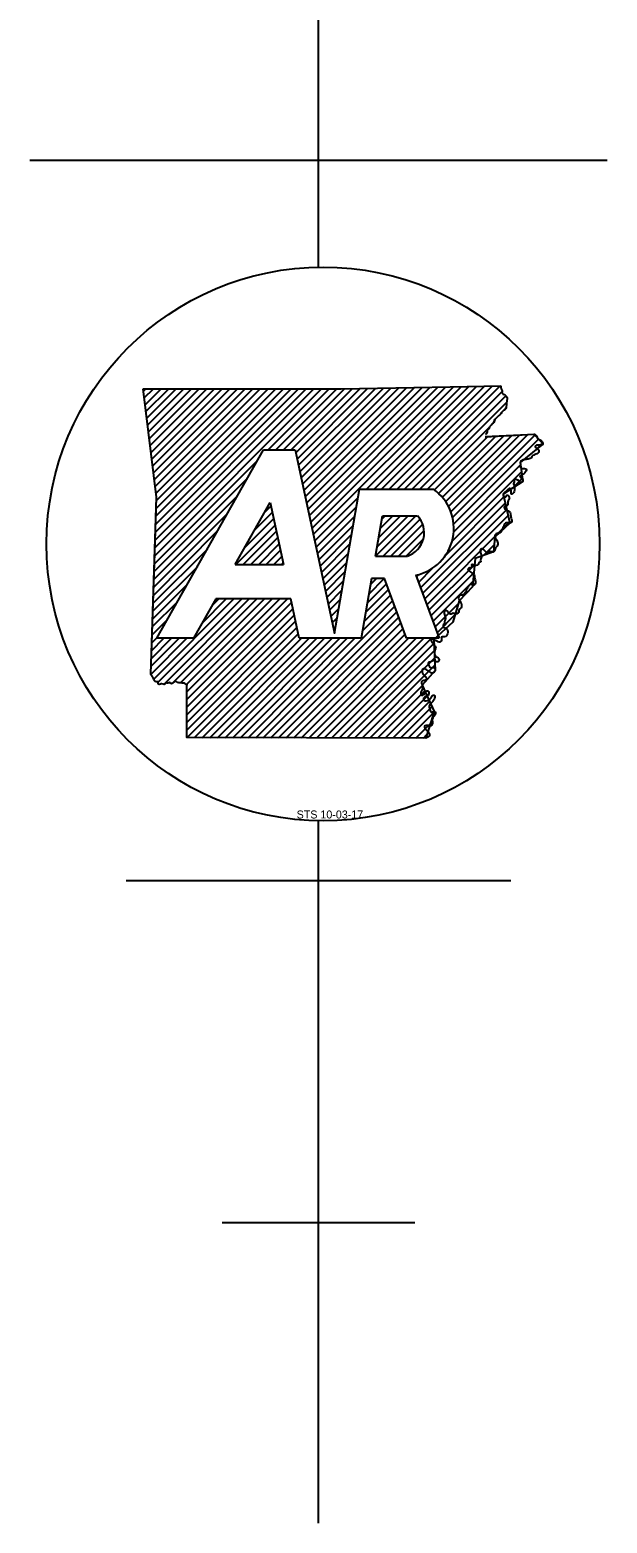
# Model space of a CAD drawing. Extents: x -43543 to 34500, y -13675 to 11152.
# Drawn here: x 16425 to 16951, y -3693 to -2333 of the extents above; entities that cross this region are included whole.
import ezdxf

# ---------------------------------------------------------------- set-up
doc = ezdxf.new("R2010")
doc.units = 0
doc.layers.add('R_Annotation', color=7, linetype='Continuous')

msp = doc.modelspace()

# ---------------------------------------------------------------- linework, layer by layer
at = {"layer": 'R_Annotation'}
for p, q in [((16687.9, -2548.9), (16687.9, -973)), ((16424.7, -2451.4), (16951, -2451.4)), ((16528.2, -2661.8), (16530.4, -2659.6)), ((16529, -2667.9), (16537.4, -2659.6)), ((16529.8, -2674.1), (16544.3, -2659.6)), ((16530.5, -2680.3), (16551.3, -2659.6)), ((16531.3, -2686.5), (16558.2, -2659.6)), ((16532.1, -2692.7), (16565.2, -2659.6)), ((16532.9, -2698.9), (16572.2, -2659.6)), ((16533.6, -2705.1), (16579.1, -2659.6)), ((16534.4, -2711.3), (16586.1, -2659.6)), ((16535.2, -2717.5), (16593, -2659.6)), ((16535.9, -2723.7), (16600, -2659.6)), ((16536.7, -2729.9), (16607, -2659.6)), ((16537.5, -2736.1), (16613.9, -2659.6)), ((16538.3, -2742.3), (16620.9, -2659.6)), ((16538.5, -2811.7), (16690.7, -2659.5)), ((16538.7, -2804.5), (16683.7, -2659.5)), ((16539, -2797.3), (16676.7, -2659.5)), ((16539, -2748.5), (16627.9, -2659.6)), ((16539.2, -2790.1), (16669.7, -2659.5)), ((16539.4, -2782.9), (16662.8, -2659.6)), ((16539.7, -2775.7), (16655.8, -2659.6)), ((16539.8, -2754.7), (16634.8, -2659.6)), ((16539.9, -2768.5), (16648.8, -2659.6)), ((16540.2, -2761.3), (16641.8, -2659.6)), ((16641.9, -2715.2), (16697.7, -2659.5)), ((16648.9, -2715.2), (16704.7, -2659.5)), ((16655.9, -2715.2), (16711.7, -2659.4)), ((16662.8, -2715.2), (16718.8, -2659.3)), ((16667.2, -2717.9), (16725.8, -2659.2)), ((16668.4, -2723.6), (16732.9, -2659.1)), ((16669.6, -2729.3), (16740, -2659)), ((16670.8, -2735.1), (16747.1, -2658.9)), ((16672.1, -2740.8), (16754.1, -2658.7)), ((16673.3, -2746.5), (16761.2, -2658.6)), ((16674.5, -2752.3), (16768.3, -2658.5)), ((16675.8, -2758), (16775.4, -2658.4)), ((16677, -2763.8), (16782.4, -2658.3)), ((16678.2, -2769.5), (16789.5, -2658.2)), ((16679.4, -2775.2), (16796.6, -2658.1)), ((16680.7, -2781), (16803.7, -2658)), ((16681.9, -2786.7), (16810.8, -2657.8)), ((16683.1, -2792.4), (16817.9, -2657.7)), ((16731.5, -2751), (16825, -2657.5)), ((16738.5, -2751), (16832.2, -2657.3)), ((16745.4, -2751), (16839.3, -2657.2)), ((16752.4, -2751), (16846.4, -2657)), ((16759.4, -2751), (16853.5, -2656.9)), ((16766.3, -2751), (16855.1, -2662.3)), ((16773.3, -2751), (16858.5, -2665.9)), ((16780.3, -2751), (16859.4, -2671.9)), ((16787.2, -2751), (16843.5, -2694.8)), ((16793.6, -2751.7), (16842.1, -2703.1)), ((16797.4, -2754.8), (16849.4, -2702.8)), ((16800.8, -2758.4), (16856.8, -2702.4)), ((16803.8, -2762.3), (16864.1, -2702)), ((16806.4, -2766.7), (16871.5, -2701.6)), ((16808.5, -2771.6), (16878.8, -2701.3)), ((16810.1, -2776.9), (16885.4, -2701.6)), ((16811, -2782.9), (16888.7, -2705.3)), ((16540.6, -2886.8), (16637.7, -2715.2)), ((16637.7, -2715.2), (16666.6, -2715.2)), ((16885.6, -2715.4), (16891.9, -2709)), ((16538.2, -2818.9), (16632.2, -2724.9)), ((16811.1, -2789.9), (16872, -2728.9)), ((16538, -2826.1), (16623.1, -2741)), ((16809.6, -2798.3), (16872.8, -2735.1)), ((16865, -2749.8), (16873.6, -2741.2)), ((16537.8, -2833.3), (16614.1, -2757)), ((16684.4, -2798.2), (16723.9, -2758.7)), ((16725.2, -2751), (16792.7, -2751)), ((16803.6, -2811.3), (16856.8, -2758.1)), ((16537.5, -2840.5), (16605, -2773.1)), ((16612, -2819.5), (16643.8, -2763.3)), ((16629.8, -2788.1), (16645.7, -2772.2)), ((16638.9, -2772.1), (16644.5, -2766.5)), ((16685.6, -2803.9), (16722.4, -2767.1)), ((16780.9, -2841), (16858.1, -2763.8)), ((16782.7, -2846.1), (16859.4, -2769.4)), ((16612.4, -2819.5), (16648.2, -2783.7)), ((16620.7, -2804.2), (16646.9, -2777.9)), ((16686.8, -2809.7), (16720.9, -2775.5)), ((16688, -2815.4), (16719.5, -2784)), ((16739.9, -2811.9), (16776.5, -2775.2)), ((16741.3, -2803.5), (16769.6, -2775.2)), ((16742.8, -2795.1), (16762.6, -2775.2)), ((16744.3, -2786.6), (16755.6, -2775.2)), ((16745.7, -2778.2), (16748.7, -2775.2)), ((16746.2, -2775.2), (16777.9, -2775.2)), ((16746.9, -2811.9), (16780.4, -2778.3)), ((16753.8, -2811.9), (16782.8, -2782.9)), ((16784.6, -2851.2), (16860.7, -2775.1)), ((16786.5, -2856.2), (16862, -2780.7)), ((16537.3, -2847.7), (16595.9, -2789.1)), ((16619.3, -2819.5), (16649.4, -2789.4)), ((16626.3, -2819.5), (16650.6, -2795.2)), ((16633.3, -2819.5), (16651.9, -2800.9)), ((16689.3, -2821.1), (16718, -2792.4)), ((16690.5, -2826.9), (16716.5, -2800.8)), ((16760.8, -2811.9), (16784.1, -2788.6)), ((16767.8, -2811.9), (16783.5, -2796.2)), ((16537, -2854.9), (16586.8, -2805.2)), ((16640.2, -2819.5), (16653.1, -2806.6)), ((16647.2, -2819.5), (16654.3, -2812.4)), ((16691.7, -2832.6), (16715.1, -2809.3)), ((16739.9, -2811.9), (16768.8, -2811.9)), ((16838.2, -2811.5), (16848, -2801.8)), ((16536.8, -2862.1), (16577.7, -2821.3)), ((16612, -2819.5), (16655.8, -2819.5)), ((16654.2, -2819.5), (16655.5, -2818.1)), ((16692.9, -2838.3), (16713.6, -2817.7)), ((16694.2, -2844.1), (16712.1, -2826.1)), ((16779, -2835.9), (16792.2, -2822.6)), ((16788.4, -2861.3), (16830.2, -2819.5)), ((16790.3, -2866.4), (16829.4, -2827.3)), ((16536.6, -2869.3), (16568.6, -2837.3)), ((16695.4, -2849.8), (16710.6, -2834.6)), ((16732.4, -2854.6), (16749.8, -2837.2)), ((16733.9, -2846.2), (16747.8, -2832.3)), ((16735.3, -2837.7), (16740.8, -2832.3)), ((16748, -2832.3), (16736.3, -2832.3)), ((16768.2, -2886.8), (16748, -2832.3)), ((16776.6, -2829.3), (16797.8, -2886.8)), ((16777.1, -2830.8), (16779.2, -2828.7)), ((16792.1, -2871.5), (16828.6, -2835)), ((16536.3, -2876.5), (16559.5, -2853.4)), ((16537.6, -2924), (16610.8, -2850.8)), ((16541.7, -2926.9), (16617.8, -2850.8)), ((16546.7, -2928.8), (16624.7, -2850.8)), ((16555, -2927.5), (16631.7, -2850.8)), ((16562.1, -2927.4), (16638.7, -2850.8)), ((16567.6, -2928.9), (16645.6, -2850.8)), ((16567.8, -2942.6), (16659.6, -2850.8)), ((16567.8, -2935.6), (16652.6, -2850.8)), ((16567.8, -2949.5), (16663.2, -2854.1)), ((16594.3, -2850.8), (16573.9, -2886.8)), ((16581.8, -2872.9), (16603.8, -2850.8)), ((16590.9, -2856.8), (16596.9, -2850.8)), ((16662.5, -2850.8), (16594.3, -2850.8)), ((16696.6, -2855.6), (16709.2, -2843)), ((16697.9, -2861.3), (16707.7, -2851.4)), ((16728, -2879.9), (16755.5, -2852.5)), ((16729.5, -2871.5), (16753.6, -2847.4)), ((16730.9, -2863), (16751.7, -2842.3)), ((16794, -2876.6), (16815.4, -2855.2)), ((16567.8, -2956.5), (16664.5, -2859.9)), ((16567.9, -2963.4), (16665.7, -2865.6)), ((16637.5, -2977.3), (16757.3, -2857.5)), ((16644.5, -2977.4), (16759.2, -2862.6)), ((16651.4, -2977.4), (16761.1, -2867.7)), ((16699.1, -2867), (16706.2, -2859.9)), ((16700.3, -2872.8), (16704.8, -2868.3)), ((16795.9, -2881.7), (16812.4, -2865.2)), ((16536.1, -2883.7), (16550.4, -2869.4)), ((16567.9, -2970.4), (16666.9, -2871.3)), ((16568, -2977.2), (16668.2, -2877.1)), ((16658.4, -2977.4), (16763, -2872.8)), ((16665.4, -2977.4), (16764.9, -2877.9)), ((16701.5, -2878.5), (16703.3, -2876.8)), ((16535, -2919.7), (16567.8, -2886.8)), ((16535.1, -2912.6), (16560.9, -2886.8)), ((16535.4, -2905.4), (16553.9, -2886.8)), ((16535.6, -2898.2), (16546.9, -2886.8)), ((16535.9, -2891), (16541.3, -2885.5)), ((16573.9, -2886.8), (16540.6, -2886.8)), ((16574.9, -2977.2), (16669.4, -2882.8)), ((16581.9, -2977.3), (16672.3, -2886.8)), ((16588.9, -2977.3), (16679.3, -2886.8)), ((16595.8, -2977.3), (16686.3, -2886.8)), ((16602.8, -2977.3), (16693.2, -2886.8)), ((16609.7, -2977.3), (16700.2, -2886.8)), ((16616.7, -2977.3), (16707.2, -2886.8)), ((16623.6, -2977.3), (16714.1, -2886.8)), ((16630.6, -2977.3), (16721.1, -2886.8)), ((16726.8, -2886.8), (16670.2, -2886.8)), ((16672.3, -2977.4), (16766.7, -2883)), ((16679.3, -2977.4), (16769.8, -2886.8)), ((16686.2, -2977.4), (16776.8, -2886.8)), ((16693.2, -2977.4), (16783.8, -2886.8)), ((16700.1, -2977.4), (16790.7, -2886.8)), ((16707.1, -2977.5), (16793.1, -2891.5)), ((16797.8, -2886.8), (16768.2, -2886.8)), ((16714, -2977.5), (16793.4, -2898.1)), ((16721, -2977.5), (16793.7, -2904.8)), ((16727.9, -2977.5), (16794, -2911.4)), ((16734.9, -2977.5), (16782.6, -2929.8)), ((16741.8, -2977.5), (16784.7, -2934.6)), ((16748.8, -2977.5), (16786.9, -2939.5)), ((16755.8, -2977.5), (16789, -2944.3)), ((16762.7, -2977.6), (16791.2, -2949.1)), ((16769.7, -2977.6), (16793, -2954.3)), ((16776.6, -2977.6), (16789.8, -2964.4)), ((16783.6, -2977.6), (16786.7, -2974.5)), ((16687.9, -3692.5), (16687.9, -3053)), ((16512.4, -3107.3), (16863.3, -3107.3)), ((16600.1, -3418.9), (16775.6, -3418.9))]:
    msp.add_line(p, q, dxfattribs=at)
for points in [[(16527.9, -2659.6), (16624, -2659.6), (16708.4, -2659.5), (16807.9, -2657.9), (16854, -2656.8)], [(16538.6, -2809), (16540.2, -2758.3), (16527.9, -2659.6)], [(16528, -2659.6), (16624.1, -2659.6), (16708.4, -2659.5), (16807.9, -2657.9), (16854, -2656.8)], [(16534.9, -2919.6), (16540.3, -2758.3), (16528, -2659.6)], [(16884.2, -2701), (16892.5, -2709.7), (16871.8, -2726.7), (16874, -2743.9), (16856.2, -2755.7), (16862.3, -2782.1), (16848.6, -2794.6), (16847.4, -2808.2), (16830.7, -2814.2), (16828.1, -2839.9), (16816.1, -2852.7), (16810.4, -2872), (16792.9, -2888), (16794.2, -2916.1), (16782.4, -2929.4), (16793.2, -2953.6), (16785.7, -2977.6)], [(16839.7, -2703.3), (16884.8, -2700.9)], [(16839.7, -2703.2), (16884.8, -2701)], [(16666.6, -2715.2), (16702.3, -2882.2), (16725.2, -2751)], [(16643.8, -2763.3), (16655.8, -2819.5)], [(16739.9, -2811.9), (16746.2, -2775.2)], [(16534.9, -2919.6), (16538.6, -2809)], [(16736.3, -2832.3), (16726.8, -2886.8)], [(16670.2, -2886.8), (16662.5, -2850.8)], [(16785.7, -2977.6), (16567.9, -2977.2), (16567.8, -2929.1)], [(16785.7, -2977.6), (16567.9, -2977.2), (16567.8, -2929.2)]]:
    msp.add_lwpolyline(points, dxfattribs=at)
msp.add_ellipse((16692, -2800.9), major_axis=(252.1, 0), ratio=0.999976, dxfattribs=at)
for centre, major_axis, start_param, end_param in [((16767.6, -2786.7), (-43.6, 0), 1.777838, 4.099264), ((16761.9, -2790.7), (-22.3, 0), 1.887169, 3.90762)]:
    msp.add_ellipse(centre, major_axis=major_axis, ratio=0.999987, start_param=start_param, end_param=end_param, dxfattribs=at)
for points in [[(16854, -2656.8), (16854.3, -2659.5), (16855.1, -2660.8), (16855.2, -2663.3), (16856.2, -2664.4), (16858, -2665.5), (16859.5, -2667.2), (16859.9, -2669.2), (16859.4, -2671.3), (16859.3, -2673.6), (16859, -2675.7), (16858.6, -2677.4), (16857.3, -2679), (16855.9, -2680), (16854.7, -2681.2), (16853.8, -2682.6), (16852.2, -2684), (16850.7, -2685.5), (16849.4, -2686.8), (16848.1, -2688.5), (16847.5, -2690.3), (16846.2, -2691.6), (16845.1, -2692.8), (16843.7, -2694.4), (16843, -2696), (16841.7, -2697.8), (16841.3, -2699.6), (16840.5, -2701), (16840.4, -2701.3)], [(16854, -2656.8), (16854.3, -2659.5), (16855.1, -2660.8), (16855.2, -2663.3), (16856.2, -2664.4), (16858, -2665.5), (16859.5, -2667.2), (16859.9, -2669.2), (16859.4, -2671.3), (16859.3, -2673.6), (16859, -2675.6), (16858.7, -2677.5), (16857.3, -2679), (16855.9, -2680), (16854.6, -2681.3), (16853.8, -2682.6), (16852.2, -2684), (16850.7, -2685.5), (16849.4, -2686.8), (16848.2, -2688.5), (16847.6, -2690.3), (16846.2, -2691.6), (16845.1, -2692.8), (16843.7, -2694.4), (16843, -2696), (16841.6, -2697.8), (16841.3, -2699.6), (16840.4, -2701.1), (16840.4, -2701.3)], [(16884.2, -2701), (16884.8, -2701), (16886.8, -2703.1), (16887.7, -2704.9), (16889.1, -2705.9), (16890.6, -2706.4), (16891.7, -2707.8), (16892.4, -2709.3), (16892, -2710.6), (16890.3, -2710.7), (16888.5, -2711), (16886.7, -2710.9), (16885.3, -2712.2), (16886.6, -2713.7), (16888.3, -2715.2), (16888.8, -2716.8), (16887.9, -2718.3), (16885.9, -2719.2), (16884.1, -2719.9), (16882.4, -2721.3), (16881.6, -2722.7), (16879.8, -2723.3), (16877.9, -2723.8), (16876.3, -2724), (16874.4, -2724.4), (16872.5, -2725.3), (16871.8, -2726.8), (16872, -2729), (16871.9, -2731.3), (16873.9, -2732.1), (16875.6, -2732.2), (16877.3, -2733), (16877.1, -2734.3), (16875.9, -2736), (16874.4, -2737.3), (16872.9, -2738), (16871.5, -2739.2), (16872, -2740.5), (16873.2, -2741.3), (16874.1, -2742.7), (16874, -2743.9), (16872.6, -2744.8), (16871, -2744.4), (16869.9, -2742.9), (16868.6, -2742.5), (16867.5, -2741.9), (16866.2, -2742.7), (16866.2, -2744.4), (16865.7, -2746.3), (16866.1, -2747.6), (16866.6, -2749.5), (16866.6, -2751), (16866.1, -2753), (16865.1, -2755.1), (16863.9, -2755.7), (16863.4, -2753.5), (16863.2, -2751.6), (16862.5, -2750.5), (16861.5, -2750.5), (16860.3, -2751.4), (16858.9, -2752.8), (16857.2, -2754.3), (16856.2, -2755.7), (16856.7, -2757.6), (16858, -2758), (16859, -2757.7), (16859.6, -2756.5), (16860.5, -2756.4), (16861.5, -2758.2)], [(16861.5, -2758.2), (16861.8, -2759.9), (16860.8, -2761.7), (16860.4, -2763.6), (16860.5, -2765.4), (16858.6, -2766.4), (16857, -2767.6), (16858, -2769.1), (16859.8, -2770.4), (16861.5, -2771.3), (16862.6, -2772.4), (16862.9, -2774.8), (16863.3, -2776.4), (16863.9, -2778.5), (16864.1, -2780), (16863, -2781.8), (16861.8, -2782.1), (16860.4, -2781.7), (16858.9, -2781.6), (16857.7, -2782.7), (16856.8, -2784.4), (16855.9, -2786.1), (16855.2, -2787.5), (16854.6, -2789.1), (16853.3, -2790.9), (16851.7, -2791.1), (16849.8, -2791.6), (16848.6, -2792.9), (16848.8, -2795.1), (16849.9, -2796.6), (16850.7, -2798.4), (16851.3, -2800.1), (16851, -2802.1), (16850.2, -2803.6), (16849.1, -2804.5), (16848.6, -2806.4), (16847.8, -2807.8), (16847.2, -2808.3), (16845.7, -2808.2), (16844.2, -2807.9), (16842.9, -2808), (16841.7, -2808.6), (16840.4, -2808.2), (16839.1, -2806.8), (16838, -2805.7), (16836.8, -2805.3), (16835.5, -2806), (16835.4, -2807.9), (16835.9, -2809.9), (16836.5, -2812.7), (16835.9, -2814.3), (16835.7, -2817.1)], [(16835.7, -2817.1), (16833.7, -2818.7), (16832.7, -2820.3), (16827.4, -2819.8), (16827.6, -2821.7), (16825.7, -2822.7), (16824, -2823.9), (16825, -2825.3), (16826.8, -2826.6), (16828.6, -2827.6), (16829.7, -2828.6), (16830, -2831.1), (16830.3, -2832.6), (16830.9, -2834.8), (16831.1, -2836.2), (16830, -2838), (16828.8, -2838.4), (16827.5, -2837.9), (16826, -2837.8), (16824.7, -2839), (16823.8, -2840.7), (16822.9, -2842.4), (16822.3, -2843.8), (16821.6, -2845.3), (16820.3, -2847.1), (16818.7, -2847.4), (16816.8, -2847.9), (16815.7, -2849.2), (16815.9, -2851.4), (16816.9, -2852.9), (16817.7, -2854.7), (16818.3, -2856.3), (16818.1, -2858.3), (16817.2, -2859.8), (16816.2, -2860.7), (16815.7, -2862.6), (16814.9, -2864.1), (16814.2, -2864.5), (16812.8, -2864.4), (16811.2, -2864.1), (16809.9, -2864.2), (16808.7, -2864.9), (16807.4, -2864.4), (16806.1, -2863), (16805, -2862), (16803.8, -2861.5), (16802.6, -2862.2), (16802.4, -2864.2), (16803, -2866.2), (16803.5, -2868.9), (16803, -2870.6), (16802.8, -2873.3)], [(16802.8, -2873.3), (16802.6, -2873.4), (16801.6, -2874.8), (16802.2, -2876.9), (16804.5, -2877.7), (16805.5, -2879.7), (16805.6, -2881.5), (16804.9, -2883.9), (16803.8, -2885.1), (16801.7, -2885.5), (16800.1, -2885.8), (16799.9, -2888.6), (16799.1, -2889.9), (16797.9, -2890.3), (16796.1, -2889.5), (16795, -2889), (16793.7, -2888.4), (16792.1, -2887.5), (16790.8, -2887.6), (16791.2, -2890.2), (16791.3, -2890.3), (16792.7, -2892.3), (16794.1, -2893.9), (16794.8, -2895.7)], [(16802.8, -2873.3), (16802.6, -2873.4), (16801.6, -2874.8), (16802.2, -2876.9), (16804.5, -2877.7), (16805.5, -2879.7), (16805.6, -2881.5), (16804.9, -2883.9), (16803.8, -2885.1), (16801.7, -2885.5), (16800.1, -2885.8), (16799.9, -2888.6), (16799.1, -2889.9), (16797.9, -2890.3), (16796.1, -2889.5), (16795, -2889), (16793.7, -2888.4), (16792.1, -2887.5), (16790.8, -2887.6), (16791.2, -2890.2), (16791.3, -2890.3), (16792.7, -2892.3), (16794.1, -2893.9), (16794.8, -2895.7)], [(16794.8, -2895.7), (16794.2, -2897.1), (16793.5, -2899.4), (16793.7, -2901.4), (16794.6, -2903.2), (16796, -2904.1), (16797.6, -2905.5), (16797.5, -2907.6), (16796.6, -2908.3), (16794.5, -2907.8), (16792.9, -2907.1), (16791.5, -2907.5), (16789.7, -2908.4), (16788.3, -2908.6), (16788.4, -2911.5), (16790.2, -2913.5), (16791.8, -2913.5), (16793.7, -2913.7), (16794.3, -2915.8), (16793.2, -2917.6), (16791.5, -2918.5), (16789.2, -2917.4), (16787.6, -2916.3), (16786, -2915.2), (16784, -2914.7), (16782.8, -2914.9), (16782.3, -2917.4), (16783.3, -2919.7), (16784.8, -2921.3), (16786.2, -2923.3), (16786, -2924.8), (16784.9, -2925.2), (16783, -2925.6), (16781.9, -2926.2), (16781.6, -2926.6), (16782.2, -2928.7), (16782.7, -2930.9), (16782.7, -2932.6), (16782.1, -2934), (16781.1, -2936.4), (16781.2, -2938), (16781.9, -2938.7), (16782.8, -2938.5), (16784, -2937.7), (16784.8, -2936.7), (16785.4, -2935.5), (16786.6, -2934.5), (16788.2, -2935.4), (16788.5, -2937.2), (16787.7, -2938.8), (16786.4, -2939.6), (16784.9, -2940.2), (16783.7, -2941.4), (16784, -2943), (16784.9, -2943.8), (16787.2, -2943.4), (16788.6, -2942.7), (16789.5, -2942), (16790.5, -2940.9), (16791, -2939.9), (16791.8, -2938.8), (16793.2, -2938.5), (16793.8, -2939.4), (16793.5, -2941.4), (16792.7, -2943.4), (16791.6, -2945), (16790.3, -2946.1), (16788.8, -2948.5), (16789.1, -2950.8), (16789.7, -2952.7), (16790.5, -2954), (16791.9, -2953.8), (16793.5, -2953.6), (16794.5, -2954.3), (16794.4, -2956), (16793.2, -2957.7), (16792.1, -2959.2), (16791.5, -2961.3), (16791.7, -2962.8), (16791.7, -2964.1), (16791.2, -2965.7), (16790.4, -2966.5), (16788.2, -2966.5), (16785.9, -2966.2), (16784.6, -2966.9), (16784.9, -2968.9), (16786.2, -2970.4), (16787.2, -2971.2), (16788.5, -2972.8), (16789.1, -2974.2), (16789, -2975.4), (16788.1, -2976.4), (16785.7, -2977.6)], [(16794.8, -2895.7), (16794.2, -2897.1), (16793.5, -2899.4), (16793.7, -2901.4), (16794.6, -2903.2), (16796, -2904.1), (16797.6, -2905.5), (16797.5, -2907.6), (16796.6, -2908.3), (16794.5, -2907.8), (16792.9, -2907.1), (16791.5, -2907.5), (16789.7, -2908.4), (16788.3, -2908.6), (16788.4, -2911.5), (16790.2, -2913.5), (16791.8, -2913.5), (16793.7, -2913.7), (16794.3, -2915.8), (16793.2, -2917.6), (16791.5, -2918.5), (16789.2, -2917.4), (16787.6, -2916.3), (16786, -2915.2), (16784, -2914.7), (16782.8, -2914.9), (16782.3, -2917.4), (16783.3, -2919.7), (16784.8, -2921.3), (16786.2, -2923.3), (16786, -2924.8), (16784.9, -2925.2), (16783, -2925.6), (16781.9, -2926.2), (16781.6, -2926.6), (16782.2, -2928.7), (16782.7, -2930.9), (16782.7, -2932.6), (16782.1, -2934), (16781.1, -2936.4), (16781.2, -2938), (16781.9, -2938.7), (16782.8, -2938.5), (16784, -2937.7), (16784.8, -2936.7), (16785.4, -2935.5), (16786.6, -2934.5), (16788.2, -2935.4), (16788.5, -2937.2), (16787.7, -2938.8), (16786.4, -2939.6), (16784.9, -2940.2), (16783.7, -2941.4), (16784, -2943), (16784.9, -2943.8), (16787.2, -2943.4), (16788.6, -2942.7), (16789.5, -2942), (16790.5, -2940.9), (16791, -2939.9), (16791.8, -2938.8), (16793.2, -2938.5), (16793.8, -2939.4), (16793.5, -2941.4), (16792.7, -2943.4), (16791.6, -2945), (16790.3, -2946.1), (16788.8, -2948.5), (16789.1, -2950.8), (16789.7, -2952.7), (16790.5, -2954), (16791.9, -2953.8), (16793.5, -2953.6), (16794.5, -2954.3), (16794.4, -2956), (16793.2, -2957.7), (16792.1, -2959.2), (16791.5, -2961.3), (16791.7, -2962.8), (16791.7, -2964.1), (16791.2, -2965.7), (16790.4, -2966.5), (16788.2, -2966.5), (16785.9, -2966.2), (16784.6, -2966.9), (16784.9, -2968.9), (16786.2, -2970.4), (16787.2, -2971.2), (16788.5, -2972.8), (16789.1, -2974.2), (16789, -2975.4), (16788.1, -2976.4), (16785.7, -2977.6)], [(16567.8, -2929.1), (16568, -2929.3), (16566.9, -2928.5), (16565.3, -2927.7), (16563.6, -2927.6), (16561.4, -2927.3), (16559.6, -2927.1), (16557.7, -2925.9), (16555.7, -2927.2), (16553.4, -2928.1), (16552.1, -2927), (16550.4, -2927.8), (16549.2, -2927.4), (16547.1, -2928.9), (16545.1, -2928.3), (16543.7, -2928.7), (16541.9, -2928.7), (16541.6, -2926.6), (16539.8, -2926.4), (16538.3, -2925.5), (16537.3, -2923.5), (16536.6, -2921.8), (16534.9, -2919.6)], [(16567.8, -2929.2), (16568, -2929.3), (16566.9, -2928.5), (16565.3, -2927.7), (16563.6, -2927.6), (16561.4, -2927.3), (16559.6, -2927.1), (16557.7, -2925.9), (16555.6, -2927.2), (16553.4, -2928.1), (16552.1, -2927.1), (16550.4, -2927.8), (16549.2, -2927.4), (16547.1, -2928.9), (16545.1, -2928.3), (16543.7, -2928.7), (16541.9, -2928.7), (16541.6, -2926.7), (16539.8, -2926.4), (16538.4, -2925.5), (16537.3, -2923.4), (16536.6, -2921.8), (16534.9, -2919.6)]]:
    msp.add_spline(points, degree=3, dxfattribs=at)

# ---------------------------------------------------------------- texts
msp.add_text('STS 10-03-17', height=7.288, dxfattribs=at).set_placement((16667.9, -3050.9))

doc.saveas('drawing.dxf')
